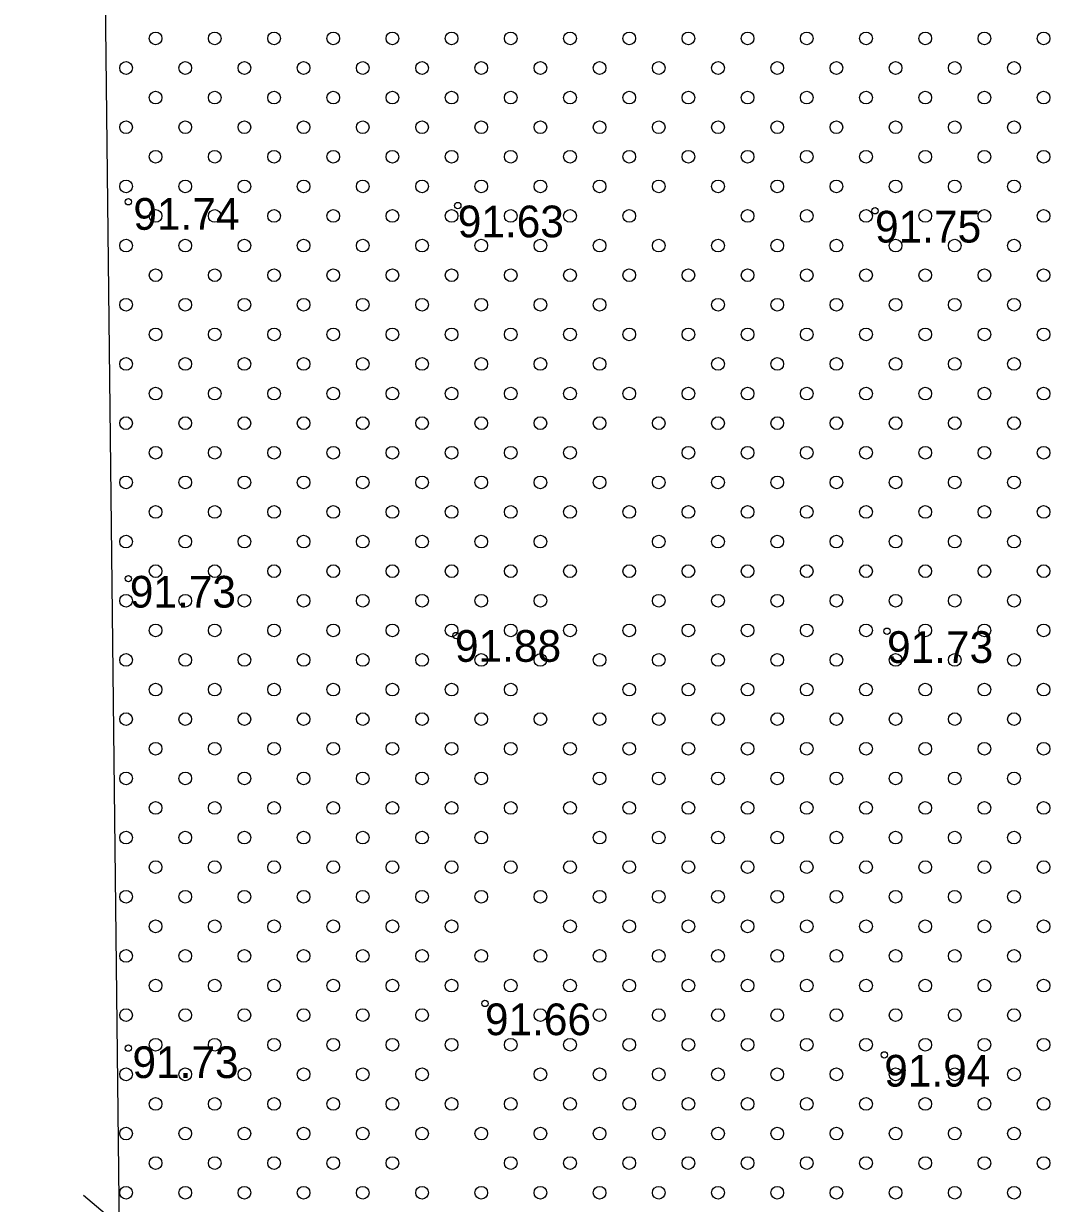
# Model space of a CAD drawing. Extents: x 316000 to 728450, y 314368 to 726000.
# Drawn here: x 725688.4 to 725810.8, y 314897.2 to 315036.8 of the extents above; entities that cross this region are included whole.
import ezdxf

# ---------------------------------------------------------------- set-up
doc = ezdxf.new("R2010")
doc.units = 0
for name, color, linetype in [('RAMI_UZMR_####_####_#', 7, 'Continuous'), ('RELJ_AATZ_####_TKST_#', 7, 'Continuous'), ('RELJ_ELEM_####_####_#', 7, 'Continuous'), ('TERT_ELEM_####_####_#', 7, 'Continuous'), ('TERT_KONT_####_####_#', 7, 'Continuous')]:
    doc.layers.add(name, color=color, linetype=linetype)

msp = doc.modelspace()

# ---------------------------------------------------------------- linework, layer by layer
at = {"layer": 'RAMI_UZMR_####_####_#'}
msp.add_lwpolyline([(727254.69, 315085.95), (727002.7, 315002.84), (726508.21, 314868.03), (726416.7, 314837.05), (725982.38, 314530.96), (725916.44, 314513.26), (725799.16, 314549.2), (725735.9, 314623.63), (725701.82, 314711.1), (725697.25, 315112.64), (725659.91, 315163.35), (725614.81, 315211.65), (725561.8, 315231.45), (725500.09, 315274.21), (725474.77, 315308.26), (725484.26, 315374.77), (725505.03, 315405.04), (725554.87, 315404.25), (725559.14, 315567.14), (725558.67, 315591.68), (725662, 315676.73), (726089.69, 315915.19)], dxfattribs=at)
at = {"layer": 'RELJ_ELEM_####_####_#'}
for centre in [(725700.78, 315015.68), (725739.73, 315015.23), (725789.07, 315014.61), (725700.78, 314971.12), (725739.53, 314964.39), (725790.49, 314964.9), (725742.94, 314920.88), (725700.78, 314915.6), (725790.16, 314914.8)]:
    msp.add_circle(centre, 0.375, dxfattribs=at)
at = {"layer": 'TERT_ELEM_####_####_#'}
for centre in [(725704, 315035), (725711, 315035), (725718, 315035), (725725, 315035), (725732, 315035), (725739, 315035), (725746, 315035), (725753, 315035), (725760, 315035), (725767, 315035), (725774, 315035), (725781, 315035), (725788, 315035), (725795, 315035), (725802, 315035), (725809, 315035), (725700.5, 315031.5), (725707.5, 315031.5), (725714.5, 315031.5), (725721.5, 315031.5), (725728.5, 315031.5), (725735.5, 315031.5), (725742.5, 315031.5), (725749.5, 315031.5), (725756.5, 315031.5), (725763.5, 315031.5), (725770.5, 315031.5), (725777.5, 315031.5), (725784.5, 315031.5), (725791.5, 315031.5), (725798.5, 315031.5), (725805.5, 315031.5), (725704, 315028), (725711, 315028), (725718, 315028), (725725, 315028), (725732, 315028), (725739, 315028), (725746, 315028), (725753, 315028), (725760, 315028), (725767, 315028), (725774, 315028), (725781, 315028), (725788, 315028), (725795, 315028), (725802, 315028), (725809, 315028), (725700.5, 315024.5), (725707.5, 315024.5), (725714.5, 315024.5), (725721.5, 315024.5), (725728.5, 315024.5), (725735.5, 315024.5), (725742.5, 315024.5), (725749.5, 315024.5), (725756.5, 315024.5), (725763.5, 315024.5), (725770.5, 315024.5), (725777.5, 315024.5), (725784.5, 315024.5), (725791.5, 315024.5), (725798.5, 315024.5), (725805.5, 315024.5), (725704, 315021), (725711, 315021), (725718, 315021), (725725, 315021), (725732, 315021), (725739, 315021), (725746, 315021), (725753, 315021), (725760, 315021), (725767, 315021), (725774, 315021), (725781, 315021), (725788, 315021), (725795, 315021), (725802, 315021), (725809, 315021), (725700.5, 315017.5), (725707.5, 315017.5), (725714.5, 315017.5), (725721.5, 315017.5), (725728.5, 315017.5), (725735.5, 315017.5), (725742.5, 315017.5), (725749.5, 315017.5), (725756.5, 315017.5), (725763.5, 315017.5), (725770.5, 315017.5), (725777.5, 315017.5), (725784.5, 315017.5), (725791.5, 315017.5), (725798.5, 315017.5), (725805.5, 315017.5), (725704, 315014), (725711, 315014), (725718, 315014), (725725, 315014), (725732, 315014), (725739, 315014), (725746, 315014), (725753, 315014), (725760, 315014), (725774, 315014), (725781, 315014), (725788, 315014), (725795, 315014), (725802, 315014), (725809, 315014), (725700.5, 315010.5), (725707.5, 315010.5), (725714.5, 315010.5), (725721.5, 315010.5), (725728.5, 315010.5), (725735.5, 315010.5), (725742.5, 315010.5), (725749.5, 315010.5), (725756.5, 315010.5), (725763.5, 315010.5), (725770.5, 315010.5), (725777.5, 315010.5), (725784.5, 315010.5), (725791.5, 315010.5), (725798.5, 315010.5), (725805.5, 315010.5), (725704, 315007), (725711, 315007), (725718, 315007), (725725, 315007), (725732, 315007), (725739, 315007), (725746, 315007), (725753, 315007), (725760, 315007), (725767, 315007), (725774, 315007), (725781, 315007), (725788, 315007), (725795, 315007), (725802, 315007), (725809, 315007), (725700.5, 315003.5), (725707.5, 315003.5), (725714.5, 315003.5), (725721.5, 315003.5), (725728.5, 315003.5), (725735.5, 315003.5), (725742.5, 315003.5), (725749.5, 315003.5), (725756.5, 315003.5), (725770.5, 315003.5), (725777.5, 315003.5), (725784.5, 315003.5), (725791.5, 315003.5), (725798.5, 315003.5), (725805.5, 315003.5), (725704, 315000), (725711, 315000), (725718, 315000), (725725, 315000), (725732, 315000), (725739, 315000), (725746, 315000), (725753, 315000), (725760, 315000), (725767, 315000), (725774, 315000), (725781, 315000), (725788, 315000), (725795, 315000), (725802, 315000), (725809, 315000), (725700.5, 314996.5), (725707.5, 314996.5), (725714.5, 314996.5), (725721.5, 314996.5), (725728.5, 314996.5), (725735.5, 314996.5), (725742.5, 314996.5), (725749.5, 314996.5), (725756.5, 314996.5), (725770.5, 314996.5), (725777.5, 314996.5), (725784.5, 314996.5), (725791.5, 314996.5), (725798.5, 314996.5), (725805.5, 314996.5), (725704, 314993), (725711, 314993), (725718, 314993), (725725, 314993), (725732, 314993), (725739, 314993), (725746, 314993), (725753, 314993), (725760, 314993), (725767, 314993), (725774, 314993), (725781, 314993), (725788, 314993), (725795, 314993), (725802, 314993), (725809, 314993), (725700.5, 314989.5), (725707.5, 314989.5), (725714.5, 314989.5), (725721.5, 314989.5), (725728.5, 314989.5), (725735.5, 314989.5), (725742.5, 314989.5), (725749.5, 314989.5), (725756.5, 314989.5), (725763.5, 314989.5), (725770.5, 314989.5), (725777.5, 314989.5), (725784.5, 314989.5), (725791.5, 314989.5), (725798.5, 314989.5), (725805.5, 314989.5), (725704, 314986), (725711, 314986), (725718, 314986), (725725, 314986), (725732, 314986), (725739, 314986), (725746, 314986), (725753, 314986), (725767, 314986), (725774, 314986), (725781, 314986), (725788, 314986), (725795, 314986), (725802, 314986), (725809, 314986), (725700.5, 314982.5), (725707.5, 314982.5), (725714.5, 314982.5), (725721.5, 314982.5), (725728.5, 314982.5), (725735.5, 314982.5), (725742.5, 314982.5), (725749.5, 314982.5), (725756.5, 314982.5), (725763.5, 314982.5), (725770.5, 314982.5), (725777.5, 314982.5), (725784.5, 314982.5), (725791.5, 314982.5), (725798.5, 314982.5), (725805.5, 314982.5), (725704, 314979), (725711, 314979), (725718, 314979), (725725, 314979), (725732, 314979), (725739, 314979), (725746, 314979), (725753, 314979), (725760, 314979), (725767, 314979), (725774, 314979), (725781, 314979), (725788, 314979), (725795, 314979), (725802, 314979), (725809, 314979), (725700.5, 314975.5), (725707.5, 314975.5), (725714.5, 314975.5), (725721.5, 314975.5), (725728.5, 314975.5), (725735.5, 314975.5), (725742.5, 314975.5), (725749.5, 314975.5), (725763.5, 314975.5), (725770.5, 314975.5), (725777.5, 314975.5), (725784.5, 314975.5), (725791.5, 314975.5), (725798.5, 314975.5), (725805.5, 314975.5), (725704, 314972), (725711, 314972), (725718, 314972), (725725, 314972), (725732, 314972), (725739, 314972), (725746, 314972), (725753, 314972), (725760, 314972), (725767, 314972), (725774, 314972), (725781, 314972), (725788, 314972), (725795, 314972), (725802, 314972), (725809, 314972), (725700.5, 314968.5), (725707.5, 314968.5), (725714.5, 314968.5), (725721.5, 314968.5), (725728.5, 314968.5), (725735.5, 314968.5), (725742.5, 314968.5), (725749.5, 314968.5), (725763.5, 314968.5), (725770.5, 314968.5), (725777.5, 314968.5), (725784.5, 314968.5), (725791.5, 314968.5), (725798.5, 314968.5), (725805.5, 314968.5), (725704, 314965), (725711, 314965), (725718, 314965), (725725, 314965), (725732, 314965), (725739, 314965), (725746, 314965), (725753, 314965), (725760, 314965), (725767, 314965), (725774, 314965), (725781, 314965), (725788, 314965), (725795, 314965), (725802, 314965), (725809, 314965), (725700.5, 314961.5), (725707.5, 314961.5), (725714.5, 314961.5), (725721.5, 314961.5), (725728.5, 314961.5), (725735.5, 314961.5), (725742.5, 314961.5), (725749.5, 314961.5), (725756.5, 314961.5), (725763.5, 314961.5), (725770.5, 314961.5), (725777.5, 314961.5), (725784.5, 314961.5), (725791.5, 314961.5), (725798.5, 314961.5), (725805.5, 314961.5), (725704, 314958), (725711, 314958), (725718, 314958), (725725, 314958), (725732, 314958), (725739, 314958), (725746, 314958), (725760, 314958), (725767, 314958), (725774, 314958), (725781, 314958), (725788, 314958), (725795, 314958), (725802, 314958), (725809, 314958), (725700.5, 314954.5), (725707.5, 314954.5), (725714.5, 314954.5), (725721.5, 314954.5), (725728.5, 314954.5), (725735.5, 314954.5), (725742.5, 314954.5), (725749.5, 314954.5), (725756.5, 314954.5), (725763.5, 314954.5), (725770.5, 314954.5), (725777.5, 314954.5), (725784.5, 314954.5), (725791.5, 314954.5), (725798.5, 314954.5), (725805.5, 314954.5), (725704, 314951), (725711, 314951), (725718, 314951), (725725, 314951), (725732, 314951), (725739, 314951), (725746, 314951), (725753, 314951), (725760, 314951), (725767, 314951), (725774, 314951), (725781, 314951), (725788, 314951), (725795, 314951), (725802, 314951), (725809, 314951), (725700.5, 314947.5), (725707.5, 314947.5), (725714.5, 314947.5), (725721.5, 314947.5), (725728.5, 314947.5), (725735.5, 314947.5), (725742.5, 314947.5), (725756.5, 314947.5), (725763.5, 314947.5), (725770.5, 314947.5), (725777.5, 314947.5), (725784.5, 314947.5), (725791.5, 314947.5), (725798.5, 314947.5), (725805.5, 314947.5), (725704, 314944), (725711, 314944), (725718, 314944), (725725, 314944), (725732, 314944), (725739, 314944), (725746, 314944), (725753, 314944), (725760, 314944), (725767, 314944), (725774, 314944), (725781, 314944), (725788, 314944), (725795, 314944), (725802, 314944), (725809, 314944), (725700.5, 314940.5), (725707.5, 314940.5), (725714.5, 314940.5), (725721.5, 314940.5), (725728.5, 314940.5), (725735.5, 314940.5), (725742.5, 314940.5), (725756.5, 314940.5), (725763.5, 314940.5), (725770.5, 314940.5), (725777.5, 314940.5), (725784.5, 314940.5), (725791.5, 314940.5), (725798.5, 314940.5), (725805.5, 314940.5), (725704, 314937), (725711, 314937), (725718, 314937), (725725, 314937), (725732, 314937), (725739, 314937), (725746, 314937), (725753, 314937), (725760, 314937), (725767, 314937), (725774, 314937), (725781, 314937), (725788, 314937), (725795, 314937), (725802, 314937), (725809, 314937), (725700.5, 314933.5), (725707.5, 314933.5), (725714.5, 314933.5), (725721.5, 314933.5), (725728.5, 314933.5), (725735.5, 314933.5), (725742.5, 314933.5), (725749.5, 314933.5), (725756.5, 314933.5), (725763.5, 314933.5), (725770.5, 314933.5), (725777.5, 314933.5), (725784.5, 314933.5), (725791.5, 314933.5), (725798.5, 314933.5), (725805.5, 314933.5), (725704, 314930), (725711, 314930), (725718, 314930), (725725, 314930), (725732, 314930), (725739, 314930), (725753, 314930), (725760, 314930), (725767, 314930), (725774, 314930), (725781, 314930), (725788, 314930), (725795, 314930), (725802, 314930), (725809, 314930), (725700.5, 314926.5), (725707.5, 314926.5), (725714.5, 314926.5), (725721.5, 314926.5), (725728.5, 314926.5), (725735.5, 314926.5), (725742.5, 314926.5), (725749.5, 314926.5), (725756.5, 314926.5), (725763.5, 314926.5), (725770.5, 314926.5), (725777.5, 314926.5), (725784.5, 314926.5), (725791.5, 314926.5), (725798.5, 314926.5), (725805.5, 314926.5), (725704, 314923), (725711, 314923), (725718, 314923), (725725, 314923), (725732, 314923), (725739, 314923), (725746, 314923), (725753, 314923), (725760, 314923), (725767, 314923), (725774, 314923), (725781, 314923), (725788, 314923), (725795, 314923), (725802, 314923), (725809, 314923), (725700.5, 314919.5), (725707.5, 314919.5), (725714.5, 314919.5), (725721.5, 314919.5), (725728.5, 314919.5), (725735.5, 314919.5), (725749.5, 314919.5), (725756.5, 314919.5), (725763.5, 314919.5), (725770.5, 314919.5), (725777.5, 314919.5), (725784.5, 314919.5), (725791.5, 314919.5), (725798.5, 314919.5), (725805.5, 314919.5), (725704, 314916), (725711, 314916), (725718, 314916), (725725, 314916), (725732, 314916), (725739, 314916), (725746, 314916), (725753, 314916), (725760, 314916), (725767, 314916), (725774, 314916), (725781, 314916), (725788, 314916), (725795, 314916), (725802, 314916), (725809, 314916), (725700.5, 314912.5), (725707.5, 314912.5), (725714.5, 314912.5), (725721.5, 314912.5), (725728.5, 314912.5), (725735.5, 314912.5), (725749.5, 314912.5), (725756.5, 314912.5), (725763.5, 314912.5), (725770.5, 314912.5), (725777.5, 314912.5), (725784.5, 314912.5), (725791.5, 314912.5), (725798.5, 314912.5), (725805.5, 314912.5), (725704, 314909), (725711, 314909), (725718, 314909), (725725, 314909), (725732, 314909), (725739, 314909), (725746, 314909), (725753, 314909), (725760, 314909), (725767, 314909), (725774, 314909), (725781, 314909), (725788, 314909), (725795, 314909), (725802, 314909), (725809, 314909), (725700.5, 314905.5), (725707.5, 314905.5), (725714.5, 314905.5), (725721.5, 314905.5), (725728.5, 314905.5), (725735.5, 314905.5), (725742.5, 314905.5), (725749.5, 314905.5), (725756.5, 314905.5), (725763.5, 314905.5), (725770.5, 314905.5), (725777.5, 314905.5), (725784.5, 314905.5), (725791.5, 314905.5), (725798.5, 314905.5), (725805.5, 314905.5), (725704, 314902), (725711, 314902), (725718, 314902), (725725, 314902), (725732, 314902), (725746, 314902), (725753, 314902), (725760, 314902), (725767, 314902), (725774, 314902), (725781, 314902), (725788, 314902), (725795, 314902), (725802, 314902), (725809, 314902), (725700.5, 314898.5), (725707.5, 314898.5), (725714.5, 314898.5), (725721.5, 314898.5), (725728.5, 314898.5), (725735.5, 314898.5), (725742.5, 314898.5), (725749.5, 314898.5), (725756.5, 314898.5), (725763.5, 314898.5), (725770.5, 314898.5), (725777.5, 314898.5), (725784.5, 314898.5), (725791.5, 314898.5), (725798.5, 314898.5), (725805.5, 314898.5)]:
    msp.add_circle(centre, 0.75, dxfattribs=at)
at = {"layer": 'TERT_KONT_####_####_#'}
msp.add_spline([(726171.05, 315177.78), (726060.22, 315058.34), (726046.85, 314926.57), (725966, 314840.49), (725918.95, 314808.85), (725841.04, 314808.85), (725695.46, 314898.17)], degree=3, dxfattribs=at)

# ---------------------------------------------------------------- texts
at = {"layer": 'RELJ_AATZ_####_TKST_#'}
for s, p in [('91.74', (725701.37, 315012.37)), ('91.63', (725739.73, 315011.48)), ('91.75', (725789.07, 315010.86)), ('91.73', (725700.95, 314967.69)), ('91.88', (725739.4, 314961.28)), ('91.73', (725790.49, 314961.15)), ('91.66', (725742.94, 314917.13)), ('91.73', (725701.26, 314912.06)), ('91.94', (725790.16, 314911.05))]:
    msp.add_text(s, height=3.75, dxfattribs=at).set_placement(p)

doc.saveas('drawing.dxf')
